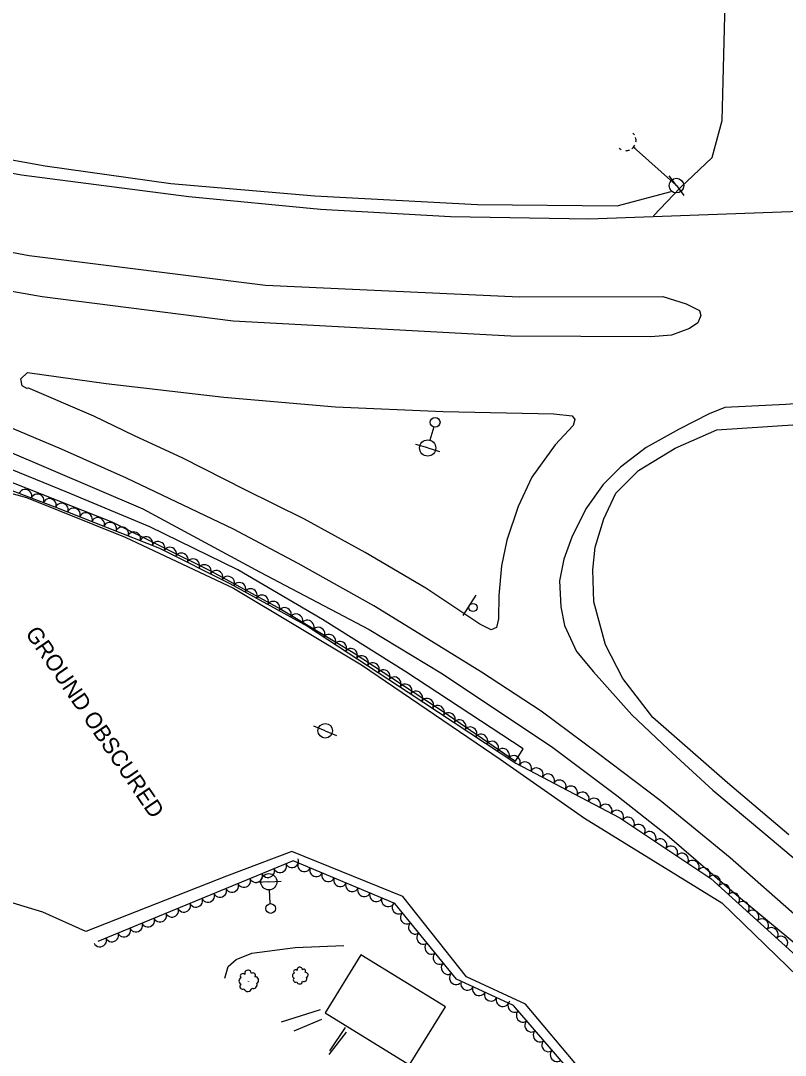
# Model space of a CAD drawing. Extents: x 1746719 to 1766531, y 631721 to 662391.
# Drawn here: x 1764239.8 to 1764475.4, y 632350 to 632668.6 of the extents above; entities that cross this region are included whole.
import ezdxf

# ---------------------------------------------------------------- set-up
doc = ezdxf.new("R2010")
doc.units = 0
for name, color, linetype in [('SURVEY - AERIAL SURVEY - Photo Control - Points - Elevations', 7, 'Continuous'), ('SURVEY - AERIAL SURVEY - Photo Control - Points - Locators', 7, 'Continuous'), ('SURVEY - AERIAL SURVEY - Photo Control with Text', 7, 'Continuous'), ('SURVEY - CENTERLINE - Existing Roads - Development', 7, 'Continuous'), ('SURVEY - CENTERLINE - Existing Roads Curve Text', 7, 'Continuous'), ('SURVEY - CENTERLINE - Existing Roads Text', 7, 'Continuous'), ('SURVEY - CONTROL - Grid', 7, 'Continuous')]:
    doc.layers.add(name, color=color, linetype=linetype)

msp = doc.modelspace()

# ---------------------------------------------------------------- linework, layer by layer
at = {"layer": 'SURVEY - AERIAL SURVEY - Photo Control - Points - Elevations'}
for points in [[(1764434.77, 632608.44), (1764443.04, 632617.09), (1764452.86, 632626.42), (1764456, 632637.85), (1764456.93, 632674.21), (1764456.28, 632691.21)], [(1764167.74, 632675.86), (1764145.98, 632667.33), (1764125.07, 632660.82), (1764108.27, 632657.23), (1764108.72, 632655.19), (1764124.4, 632650.94), (1764177.25, 632636.54), (1764247.35, 632623.92), (1764286.05, 632618.44), (1764330.4, 632614.65), (1764380.6, 632611.95), (1764423.57, 632611.6), (1764440.22, 632615.96)], [(1764144.49, 632670.6), (1764128.64, 632667.51), (1764107.34, 632664.29), (1764091.66, 632662.58), (1764072.4, 632662.38), (1764102.28, 632653.11), (1764153.73, 632638.86), (1764191, 632630.1), (1764240.05, 632621.15), (1764291.65, 632614.47), (1764332.21, 632610.52), (1764372.2, 632608.31), (1764414.91, 632607.55), (1764488.46, 632610.23)], [(1763886.33, 632651.7), (1763894.31, 632652.89), (1763916.13, 632644.98), (1763949.25, 632633.28), (1763985.56, 632621.66), (1764035.96, 632605.37), (1764078.33, 632593.11), (1764121.61, 632580.88), (1764154.74, 632565.88), (1764194.12, 632552.46), (1764234.96, 632536.47), (1764277.45, 632518.3), (1764313.44, 632498.85), (1764347.19, 632481.09), (1764369.28, 632467.73), (1764403.4, 632445.05), (1764423.53, 632430), (1764439.02, 632417.8), (1764460.41, 632399.35), (1764483.04, 632380.64)], [(1764025.46, 632651.34), (1764032.09, 632650.88), (1764079.26, 632635.44), (1764129.54, 632620.7), (1764188.44, 632606.43), (1764242.46, 632596.25), (1764315.28, 632587.11), (1764393.56, 632583.53), (1764437.72, 632583.69), (1764444.9, 632581.35), (1764449.01, 632579.38), (1764449.34, 632577.75), (1764448.44, 632575.58), (1764445.86, 632573.82), (1764440.31, 632571.74), (1764433.95, 632571.19), (1764390.89, 632571.45), (1764305.33, 632576.06), (1764246.47, 632583.5), (1764198.46, 632592), (1764136.4, 632606.27), (1764074.26, 632623.91), (1764029.05, 632639.84)], [(1764479.89, 632391.94), (1764458.47, 632410.77), (1764436.87, 632428.4), (1764417.83, 632442.84), (1764400.22, 632455.92), (1764381.77, 632467.94), (1764363.85, 632479.04), (1764348.58, 632488.34), (1764325.33, 632501.46), (1764305.42, 632511.99), (1764272.42, 632527.72), (1764252.42, 632536.6), (1764231.36, 632545.5), (1764211.86, 632553.03), (1764196.58, 632559.02), (1764181.14, 632564.2), (1764159.29, 632571.45), (1764125.93, 632581.87), (1764089.3, 632592.6), (1764054.46, 632603.46), (1764007.18, 632619.22)], [(1764646.98, 632568.83), (1764616.51, 632564.96), (1764570.87, 632559.24), (1764517.4, 632553.55), (1764475.59, 632550.38), (1764456.8, 632549.43), (1764452, 632547.56), (1764442.71, 632542.76), (1764432.54, 632537.16), (1764424.6, 632531.04), (1764419.25, 632525.8)], [(1764241.94, 632555.25), (1764240.28, 632556.15), (1764239.88, 632558.25), (1764241.87, 632560.27), (1764266.14, 632556.8), (1764302.45, 632552.65), (1764336.85, 632549.7), (1764369.95, 632548.2), (1764404.04, 632547.51), (1764409.77, 632546.93), (1764410.59, 632545.73), (1764410.09, 632543.89), (1764404.53, 632537.94), (1764397.35, 632528.02), (1764393.11, 632518.97), (1764389.58, 632508.58), (1764388, 632500.66), (1764387.16, 632491.61), (1764387.08, 632484.34), (1764386.42, 632481.69), (1764384.76, 632480.97), (1764381.26, 632482.7), (1764364.62, 632493.8), (1764345.93, 632504.81), (1764327.26, 632515.03), (1764309.03, 632524.15), (1764289.74, 632533.81), (1764274.84, 632540.75), (1764262.37, 632546.81), (1764242.01, 632555.48)], [(1764476.48, 632417.86), (1764457.61, 632433.87), (1764434.61, 632453.97), (1764425.36, 632466.03), (1764420.02, 632476.38), (1764416.46, 632489.64), (1764416.13, 632499.51), (1764416.87, 632506.43), (1764419.5, 632515.17), (1764423.21, 632523.05), (1764430.13, 632530.04), (1764441.49, 632536.89), (1764454.33, 632542.62), (1764519.89, 632546.9)], [(1764419.25, 632525.8), (1764413.98, 632518.24), (1764409.67, 632509.55), (1764407.2, 632502.71), (1764405.8, 632496.06), (1764406.21, 632488.03), (1764407.41, 632482.37), (1764411.07, 632474.29), (1764416.32, 632468.04), (1764428.1, 632454.87), (1764439.35, 632444.22), (1764453.04, 632431.67), (1764468.84, 632418.53), (1764485.62, 632404.31)], [(1764302.75, 632373.77), (1764303.72, 632377.28), (1764306.21, 632379.44), (1764311.03, 632381.42), (1764324.38, 632383.22), (1764339.42, 632383.8)]]:
    msp.add_lwpolyline(points, dxfattribs=at)
at = {"layer": 'SURVEY - AERIAL SURVEY - Photo Control - Points - Locators'}
for points in [[(1764174.39, 632413.37), (1764209.91, 632491.82), (1764215.45, 632517.16), (1764217.41, 632528.43), (1764241.61, 632521.75), (1764271.96, 632509.56), (1764305.37, 632493.87), (1764344.8, 632470.23), (1764387.57, 632441.2), (1764413.49, 632422.96), (1764455.89, 632396.94), (1764499.51, 632354.68)], [(1764483.07, 632302.03), (1764474.43, 632276.94), (1764432.13, 632309.94), (1764423.59, 632332.14), (1764395.41, 632365.69), (1764377.17, 632374.17), (1764357.61, 632398.87), (1764323.4, 632412.71), (1764303.22, 632405.1), (1764259.84, 632388.07), (1764246.6, 632394.08), (1764200.55, 632407.97), (1764177.68, 632412.97), (1764174.39, 632413.37)]]:
    msp.add_lwpolyline(points, dxfattribs=at)
at = {"layer": 'SURVEY - AERIAL SURVEY - Photo Control with Text'}
for points in [[(1764172.18, 632414.21), (1764203.3, 632486.8), (1764214.58, 632521.78), (1764215.86, 632529.39), (1764225.42, 632528.27), (1764250.37, 632518.92), (1764282.56, 632506.17), (1764304.31, 632495.29), (1764328.16, 632482.09), (1764359.2, 632461.85), (1764392.43, 632439.91), (1764424.43, 632423.1), (1764452.49, 632404.38), (1764486.33, 632373.71)], [(1764610.39, 632165.88), (1764616.15, 632187.16), (1764608.07, 632209.48), (1764566.92, 632235.24), (1764484.22, 632297.2), (1764475.89, 632273.13), (1764452.21, 632293.13), (1764425.39, 632315), (1764418.75, 632333.92), (1764391.71, 632365.34), (1764374.11, 632373.43), (1764355.12, 632396.77), (1764323.8, 632409.83), (1764263.58, 632385)]]:
    msp.add_lwpolyline(points, dxfattribs=at)
for centre, radius in [((1764310.02, 632372.78), 0.0365), ((1764325.92, 632374.46), 0.0288)]:
    msp.add_circle(centre, radius, dxfattribs=at)
for centre, radius, start, end in [((1764309.88, 632375.13), 1.04, 359.3758, 192.7955), ((1764324.54, 632375.71), 0.627, 41.9968, 219.316), ((1764325.81, 632376.31), 0.825, 359.3782, 192.7978), ((1764327.06, 632375.92), 0.567, 319.3575, 138.1031), ((1764308.18, 632372.86), 1.13, 117.2815, 244.1272), ((1764308.28, 632374.36), 0.794, 41.9945, 219.3136), ((1764311.46, 632374.64), 0.718, 319.3551, 138.1007), ((1764312.08, 632373.13), 1.05, 297.2389, 94.0279), ((1764324.46, 632374.52), 0.889, 117.2839, 244.1295), ((1764324.5, 632373.17), 0.69, 127.4428, 302.4431), ((1764325.76, 632372.87), 0.935, 197.1899, 353.0284), ((1764327.07, 632373.62), 0.941, 246.2941, 23.8183), ((1764327.55, 632374.73), 0.826, 297.2413, 94.0302), ((1764308.22, 632371.16), 0.873, 127.4404, 302.4407), ((1764309.82, 632370.77), 1.18, 197.1875, 353.026), ((1764311.47, 632371.72), 1.19, 246.2917, 23.8159)]:
    msp.add_arc(centre, radius, start, end, dxfattribs=at)
for centre, major_axis in [((1764241.27, 632522.33), (1.87, -0.7)), ((1764245.01, 632520.92), (1.87, -0.7)), ((1764248.76, 632519.52), (1.87, -0.7)), ((1764252.49, 632518.08), (1.86, -0.74)), ((1764256.21, 632516.6), (1.86, -0.74)), ((1764259.93, 632515.13), (1.86, -0.74)), ((1764263.64, 632513.66), (1.86, -0.74)), ((1764267.36, 632512.19), (1.86, -0.74)), ((1764271.08, 632510.71), (1.86, -0.74)), ((1764274.8, 632509.24), (1.86, -0.74)), ((1764278.52, 632507.77), (1.86, -0.74)), ((1764282.24, 632506.29), (1.86, -0.74)), ((1764285.83, 632504.53), (1.79, -0.89)), ((1764289.41, 632502.74), (1.79, -0.89)), ((1764292.98, 632500.95), (1.79, -0.89)), ((1764296.56, 632499.16), (1.79, -0.89)), ((1764300.14, 632497.37), (1.79, -0.89)), ((1764303.72, 632495.58), (1.79, -0.89)), ((1764307.23, 632493.67), (1.75, -0.97)), ((1764310.73, 632491.74), (1.75, -0.97)), ((1764314.23, 632489.8), (1.75, -0.97)), ((1764317.73, 632487.86), (1.75, -0.97)), ((1764321.23, 632485.93), (1.75, -0.97)), ((1764324.73, 632483.99), (1.75, -0.97)), ((1764328.23, 632482.05), (1.68, -1.09)), ((1764331.58, 632479.86), (1.68, -1.09)), ((1764334.93, 632477.68), (1.68, -1.09)), ((1764338.28, 632475.49), (1.68, -1.09)), ((1764341.63, 632473.31), (1.68, -1.09)), ((1764344.98, 632471.12), (1.68, -1.09)), ((1764348.33, 632468.94), (1.68, -1.09)), ((1764351.68, 632466.75), (1.68, -1.09)), ((1764355.03, 632464.57), (1.68, -1.09)), ((1764358.38, 632462.38), (1.68, -1.09)), ((1764361.72, 632460.18), (1.67, -1.1)), ((1764365.06, 632457.98), (1.67, -1.1)), ((1764368.4, 632455.78), (1.67, -1.1)), ((1764371.74, 632453.57), (1.67, -1.1)), ((1764375.07, 632451.37), (1.67, -1.1)), ((1764378.41, 632449.17), (1.67, -1.1)), ((1764381.75, 632446.96), (1.67, -1.1)), ((1764385.09, 632444.76), (1.67, -1.1)), ((1764388.43, 632442.56), (1.67, -1.1)), ((1764391.77, 632440.35), (1.67, -1.1)), ((1764395.27, 632438.42), (1.77, -0.93)), ((1764398.81, 632436.56), (1.77, -0.93)), ((1764402.35, 632434.7), (1.77, -0.93)), ((1764405.89, 632432.84), (1.77, -0.93)), ((1764409.43, 632430.98), (1.77, -0.93)), ((1764412.97, 632429.12), (1.77, -0.93)), ((1764416.51, 632427.26), (1.77, -0.93)), ((1764420.05, 632425.4), (1.77, -0.93)), ((1764423.59, 632423.54), (1.77, -0.93)), ((1764426.97, 632421.4), (1.66, -1.11)), ((1764430.3, 632419.18), (1.66, -1.11)), ((1764433.63, 632416.96), (1.66, -1.11)), ((1764436.95, 632414.74), (1.66, -1.11)), ((1764440.28, 632412.52), (1.66, -1.11)), ((1764443.61, 632410.3), (1.66, -1.11)), ((1764319.76, 632408.16), (-1.85, -0.76)), ((1764323.46, 632409.69), (-1.85, -0.76)), ((1764327.15, 632408.43), (-1.85, 0.77)), ((1764446.94, 632408.08), (1.66, -1.11)), ((1764450.26, 632405.86), (1.66, -1.11)), ((1764312.37, 632405.11), (-1.85, -0.76)), ((1764316.07, 632406.64), (-1.85, -0.76)), ((1764330.85, 632406.89), (-1.85, 0.77)), ((1764334.54, 632405.35), (-1.85, 0.77)), ((1764338.23, 632403.81), (-1.85, 0.77)), ((1764453.47, 632403.49), (1.48, -1.34)), ((1764304.97, 632402.07), (-1.85, -0.76)), ((1764308.67, 632403.59), (-1.85, -0.76)), ((1764341.92, 632402.27), (-1.85, 0.77)), ((1764345.62, 632400.73), (-1.85, 0.77)), ((1764456.43, 632400.8), (1.48, -1.34)), ((1764293.88, 632397.49), (-1.85, -0.76)), ((1764297.58, 632399.02), (-1.85, -0.76)), ((1764301.27, 632400.54), (-1.85, -0.76)), ((1764349.31, 632399.2), (-1.85, 0.77)), ((1764353, 632397.66), (-1.85, 0.77)), ((1764459.4, 632398.12), (1.48, -1.34)), ((1764286.48, 632394.44), (-1.85, -0.76)), ((1764290.18, 632395.97), (-1.85, -0.76)), ((1764356.19, 632395.45), (-1.26, 1.55)), ((1764462.36, 632395.43), (1.48, -1.34)), ((1764279.09, 632391.39), (-1.85, -0.76)), ((1764282.78, 632392.92), (-1.85, -0.76)), ((1764358.72, 632392.35), (-1.26, 1.55)), ((1764465.33, 632392.74), (1.48, -1.34)), ((1764468.29, 632390.06), (1.48, -1.34)), ((1764271.69, 632388.34), (-1.85, -0.76)), ((1764275.39, 632389.87), (-1.85, -0.76)), ((1764361.24, 632389.24), (-1.26, 1.55)), ((1764471.25, 632387.37), (1.48, -1.34)), ((1764264.29, 632385.29), (-1.85, -0.76)), ((1764267.99, 632386.82), (-1.85, -0.76)), ((1764363.77, 632386.14), (-1.26, 1.55)), ((1764474.22, 632384.69), (1.48, -1.34)), ((1764366.29, 632383.04), (-1.26, 1.55)), ((1764368.81, 632379.94), (-1.26, 1.55)), ((1764371.34, 632376.83), (-1.26, 1.55)), ((1764373.86, 632373.73), (-1.26, 1.55)), ((1764377.39, 632371.92), (-1.82, 0.83)), ((1764381.02, 632370.25), (-1.82, 0.83)), ((1764384.66, 632368.58), (-1.82, 0.83)), ((1764388.29, 632366.91), (-1.82, 0.83)), ((1764391.87, 632365.16), (-1.3, 1.52)), ((1764394.47, 632362.13), (-1.3, 1.52)), ((1764397.08, 632359.09), (-1.3, 1.52)), ((1764399.69, 632356.06), (-1.3, 1.52)), ((1764402.3, 632353.03), (-1.3, 1.52)), ((1764404.91, 632350), (-1.3, 1.52))]:
    msp.add_ellipse(centre, major_axis=major_axis, ratio=0.940188, start_param=0, end_param=3.141593, dxfattribs=at)
at = {"layer": 'SURVEY - CENTERLINE - Existing Roads - Development'}
for p, q in [((1764441.88, 632617.78), (1764428.62, 632629.63)), ((1764429.14, 632629.17), (1764428.62, 632629.63)), ((1764441.88, 632617.78), (1764439.63, 632620.78)), ((1764441.88, 632617.78), (1764444.12, 632614.78)), ((1764367.1, 632543.47), (1764365.92, 632539.39)), ((1764365.23, 632536.99), (1764361.62, 632538.03)), ((1764365.23, 632536.99), (1764368.83, 632535.94)), ((1764333.64, 632449.9), (1764330.16, 632451.3)), ((1764333.64, 632449.9), (1764337.12, 632448.5)), ((1764316.28, 632403.42), (1764312.54, 632403.18)), ((1764316.28, 632403.42), (1764320.03, 632403.65)), ((1764316.71, 632396.68), (1764316.44, 632400.92))]:
    msp.add_line(p, q, dxfattribs=at)
for centre, radius in [((1764441.88, 632617.78), 2.25), ((1764367.52, 632544.91), 1.5), ((1764365.23, 632536.99), 2.5), ((1764333.64, 632449.9), 2.25), ((1764316.28, 632403.42), 2.5), ((1764316.81, 632395.18), 1.5)]:
    msp.add_circle(centre, radius, dxfattribs=at)
for start_param, end_param in [(2.883049, 3.125465), (2.156577, 2.588895), (0, 0.255182), (0.730907, 1.085951), (1.352995, 1.815775)]:
    msp.add_ellipse((1764426.32, 632631.65), major_axis=(-2.08, -2.33), ratio=0.98681, start_param=start_param, end_param=end_param, dxfattribs=at)
at = {"layer": 'SURVEY - CENTERLINE - Existing Roads Curve Text'}
msp.add_lwpolyline([(1764333.64, 632363.03), (1764359.66, 632347.03), (1764370.67, 632364.93), (1764344.64, 632380.93)], close=True, dxfattribs=at)
for points in [[(1764320.15, 632360.24), (1764332.15, 632364.04)], [(1764332.51, 632360.96), (1764324.03, 632357.4)], [(1764334.89, 632350.25), (1764340.23, 632357.06)], [(1764339.75, 632358.57), (1764335.01, 632351.31)]]:
    msp.add_lwpolyline(points, dxfattribs=at)
at = {"layer": 'SURVEY - CENTERLINE - Existing Roads Text'}
msp.add_lwpolyline([(1764229.03, 632529.51), (1764267.89, 632514.22), (1764298.3, 632499.18), (1764320.2, 632487.23), (1764342.23, 632474.02), (1764369.95, 632455.89), (1764392.32, 632440.57), (1764394.59, 632444.36), (1764358.46, 632468.1), (1764332.85, 632484.14), (1764306.69, 632499.48), (1764279.62, 632512.75), (1764254.08, 632523.34), (1764227.01, 632534.34)], dxfattribs=at)
at = {"layer": 'SURVEY - CONTROL - Grid'}
msp.add_line((1764376.11, 632485.37), (1764380.16, 632491.68), dxfattribs=at)
msp.add_circle((1764379.18, 632487.88), 1.25, dxfattribs=at)

# ---------------------------------------------------------------- texts
at = {"layer": 'SURVEY - AERIAL SURVEY - Photo Control - Points - Locators'}
msp.add_text('GROUND OBSCURED', height=5, rotation=304.3244, dxfattribs=at).set_placement((1764241.07, 632479.9))

doc.saveas('drawing.dxf')
